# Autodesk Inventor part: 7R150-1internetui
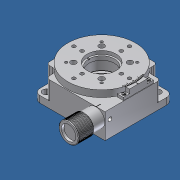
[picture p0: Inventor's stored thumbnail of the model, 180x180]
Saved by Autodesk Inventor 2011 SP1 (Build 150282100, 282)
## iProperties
Created: 2011-11
Part Number: 7R150-1internetui
Document SubType Name: Modeling
Designer: Darius
Density: 1 g/cm^3
Author: Darius
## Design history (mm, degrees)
feature "Base1"
body "Solid1"
